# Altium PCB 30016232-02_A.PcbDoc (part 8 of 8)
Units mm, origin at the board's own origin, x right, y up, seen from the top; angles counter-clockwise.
Board outline 210 x 130 mm, 8 copper layers (1-TOP, 2-GND, 3-INTOP, 4-PWR, 5-PWR, 6-INBOT, 7-GND, 8-BOTTOM), stack 1.646 mm thick; 754 components, 649 nets, 2976 pads, 2161 vias.
Unrouted connection lines stored in the file: 22.
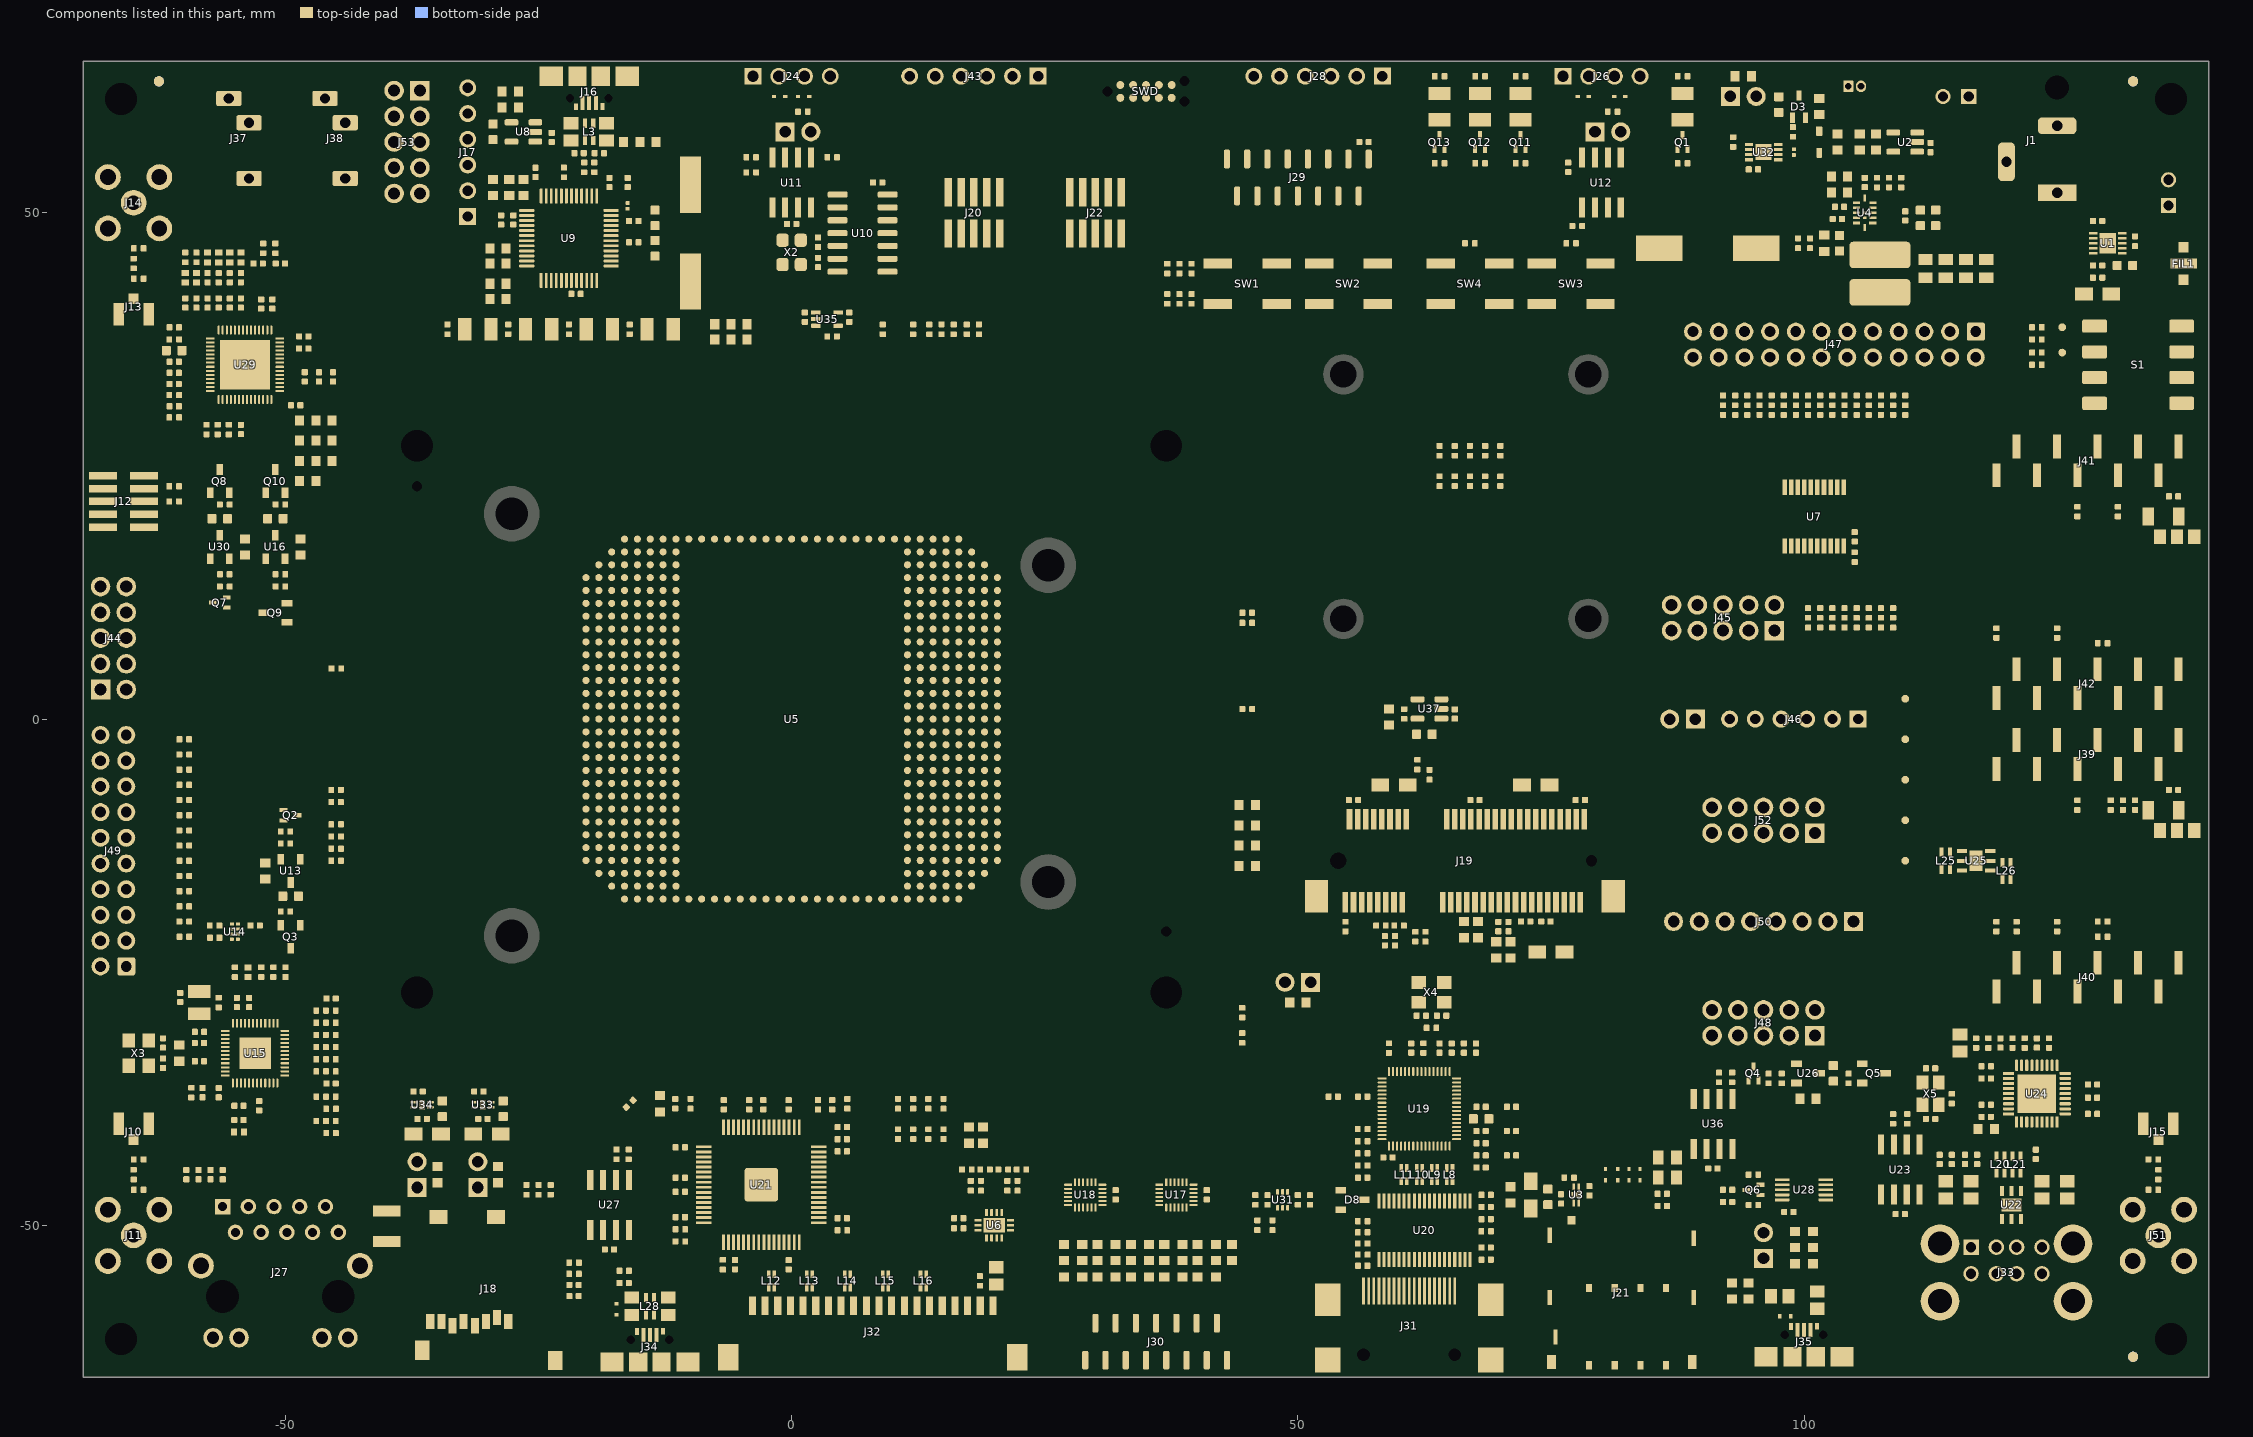
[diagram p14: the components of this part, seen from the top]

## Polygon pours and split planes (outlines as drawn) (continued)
NetJ6_2 on 1-TOP "NetJ6_2" (solid, remove dead copper, pour order 30): 45,-11.7 45.2,-11.5 49,-11.5 49.8,-12.3 49.8,-29.1 49.5,-29.4 46.4,-29.4 45,-28
GND on 1-TOP "GND" (solid, remove dead copper, pour order 28): 108.8,49.3 108.8,47.6 109,47.4 110.3,47.4 110.8,46.9 110.8,44.8 111,44.6 119,44.6 119.2,44.8 119.2,47.3 117,49.5 109,49.5
VIN_PROT on 1-TOP "VIN_PROT" (solid, remove dead copper, pour order 26): 107.1,49.9 110.283,49.9 110.783,49.4 113.7,49.4 114.1,49.8 114.1,52 113.9,52.2 110.2,52.2 110,52 109.2,52
3V3_CODEC on 1-TOP "3V3_USB" (solid, remove dead copper, pour order 20): -54.3,21.5 -53,20.2 -53,17.2 -53.2,17 -57,17 -57.2,17.2 -57.2,19.8 -55.5,21.5
1V8_SOM_EXT on 1-TOP "3V3_SOM_EXT" (solid, remove dead copper, pour order 18): -48.8,12.3 -47.5,13.6 -47.5,16.6 -47.7,16.8 -50.4,16.8 -50.6,16.6 -50.6,12.5 -50.4,12.3
1V8_CODEC on 1-TOP "3V3_USB" (solid, remove dead copper, pour order 16): -48.8,21.5 -47.5,20.2 -47.5,17.2 -47.7,17 -51.5,17 -51.7,17.2 -51.7,19.8 -50,21.5
3V3_ETH on 1-TOP "3V3_USB" (solid, remove dead copper, pour order 12): -52,-19.2 -53,-18.2 -53,-15.2 -52.8,-15 -49,-15 -48.8,-15.2 -48.8,-17.5 -50.5,-19.2
3V3_USB on 1-TOP "3V3_USB" (solid, remove dead copper, pour order 10): 104.7,-37.5 103.7,-38.5 100.7,-38.5 100.5,-38.3 100.5,-34.5 100.7,-34.3 103,-34.3 104.7,-36
VIN on 1-TOP "VIN" (solid, remove dead copper, pour order 6): 131.6,42.9 134,40.5 138.5,40.5 139,41 139,43.5 138.6,43.9 135.8,43.9 135.5,44.2 135.5,45.5 133.7,47.3 131,47.3 131,45.6 131.2,45.4 131.4,45.4 131.6,45.2
CT on 1-TOP "AGND" (solid, remove dead copper, pour order 2): -60.5,-45.2 -60.3,-45 -55.7,-45 -55.5,-45.2 -55.5,-48 -56.9,-48 -56.9,-47.2 -57.6,-46.5 -60,-46.5 -60.5,-46
GND on 3-INTOP "GND_PLANE" (solid, remove dead copper, pour order 60): -70,-65 140,-65 140,65 -70,65
5V_OUT_HDMI on 3-INTOP "5V_OUT_HDMI" (solid, remove dead copper, pour order 46): 54.5,-54.5 55.5,-55.5 67.5,-55.5 68.5,-54.5 68.5,-51 67.5,-50 55.5,-50 54.5,-51
GND on 8-BOTTOM "GND_PLANE" (solid, remove dead copper, pour order 64): -70,-65 140,-65 140,65 -70,65
3V3_RF on 8-BOTTOM "3V3_RF" (solid, remove dead copper, pour order 48): -18.872,2.337 -14.173,2.337 -13.767,2.743 -13.767,7.267 -14.3,7.8 -45.7,7.8 -47,6.5 -32,6.5 -29.107,3.607 -19.482,3.607 -19.253,3.378 -19.253,2.718
GND on 8-BOTTOM "GND" (solid, remove dead copper, pour order 50): 122,57 122.5,56.5 127.5,56.5 128,57 128,60 127.5,60.5 122.5,60.5 122,60
NetR34_2 on 8-BOTTOM "NetR34_2" (solid, remove dead copper, pour order 56): 23.443,-11.557 14.351,-11.557 13.97,-11.176 13.97,-9.144 14.351,-8.763 22.763,-8.763 24.5,-10.5
NetR33_2 on 8-BOTTOM "NetR33_2" (solid, remove dead copper, pour order 54): 23.241,-7.747 15.621,-7.747 15.24,-7.366 15.24,-5.334 15.621,-4.953 21.844,-4.953 23.241,-6.35
GND on 6-INBOT "GND_PLANE" (solid, remove dead copper, pour order 58): -70,-65 140,-65 140,65 -70,65
GND on 2-GND (split plane): 139.598,-64.598 -69.598,-64.598 -69.598,64.598 139.598,64.598
3V3 on 4-PWR (split plane): 48.893,21.893 48.924,21.869 48.961,21.854 49,21.849 75.1,21.849 75.139,21.854 75.176,21.869 75.207,21.893 85.163,31.849 104.849,31.849 104.849,19 104.854,18.961 104.869,18.924 104.893,18.893 108.349,15.437 108.349,8.563 104.937,5.151 59,5.151 58.961,5.146 58.924,5.131 58.893,5.107 44.937,-8.849 37,-8.849 36.961,-8.854 36.924,-8.869 36.893,-8.893 6.5,-39.286 5.107,-37.893 5.076,-37.869 5.061,-37.863 5.039,-37.854 5,-37.849 -18,-37.849 -18.039,-37.854 -18.065,-37.865 -18.076,-37.869 -18.107,-37.893 -22.063,-41.849 -35.937,-41.849 -37.849,-39.937 -37.849,-23 -37.854,-22.961 -37.863,-22.939 -37.869,-22.924 -37.893,-22.893 -47.849,-12.937 -47.849,5.437 -28.437,24.849 -10.5,24.849 -10.461,24.854 -10.439,24.863 -10.424,24.869 -10.393,24.893 5.063,40.349 30.437,40.349
3V3_SOM_EXT on 4-PWR (split plane): 111.849,56 111.854,55.961 111.863,55.939 111.869,55.924 111.893,55.893 112.893,54.893 112.924,54.869 112.961,54.854 113,54.849 129.937,54.849 134.849,49.937 134.849,-44.937 127.937,-51.849 95,-51.849 94.961,-51.854 94.924,-51.869 94.893,-51.893 93.893,-52.893 93.869,-52.924 93.854,-52.961 93.849,-53 93.849,-64.598 -69.598,-64.598 -69.598,64.598 111.849,64.598
3V3_ETH on 4-PWR (split plane): -50.651,-16.563 -50.651,-38.437 -54.063,-41.849 -55.937,-41.849 -60.849,-36.937 -60.849,-24.063 -52.937,-16.151 -51.063,-16.151
3V3_CODEC on 4-PWR (split plane): -45.151,37.937 -45.151,20.563 -47.563,18.151 -60.437,18.151 -60.849,18.563 -60.849,34.437 -56.437,38.849 -46.063,38.849
3V3_BOARD on 4-PWR (split plane): 118.349,42.937 118.349,39.863 115.393,36.907 115.369,36.876 115.354,36.839 115.349,36.8 115.349,35 115.354,34.961 115.369,34.924 115.393,34.893 127.849,22.437 127.849,-16.437 125.437,-18.849 116.063,-18.849 104.107,-6.893 104.076,-6.869 104.061,-6.863 104.039,-6.854 104,-6.849 98,-6.849 97.961,-6.854 97.924,-6.869 97.893,-6.893 97.163,-7.623 97.139,-7.654 97.124,-7.691 97.119,-7.73 97.119,-15.667 89.937,-22.849 81,-22.849 80.961,-22.854 80.924,-22.869 80.893,-22.893 74.937,-28.849 24.5,-28.849 24.461,-28.854 24.439,-28.863 24.424,-28.869 24.393,-28.893 18.893,-34.393 18.869,-34.424 18.854,-34.461 18.849,-34.5 18.849,-49.937 17.937,-50.849 17.063,-50.849 16.151,-49.937 16.151,-47.3 16.146,-47.261 16.131,-47.224 16.107,-47.193 11.557,-42.643 11.526,-42.619 11.511,-42.613 11.489,-42.604 11.45,-42.599 9.813,-42.599 6.714,-39.5 37.063,-9.151 45,-9.151 45.039,-9.146 45.076,-9.131 45.107,-9.107 59.063,4.849 105,4.849 105.039,4.854 105.076,4.869 105.107,4.893 108.607,8.393 108.631,8.424 108.646,8.461 108.651,8.5 108.651,15.5 108.646,15.539 108.631,15.576 108.607,15.607 105.151,19.063 105.151,41.937 106.563,43.349 117.937,43.349
VIN on 4-PWR (split plane): 139.598,-64.598 94.151,-64.598 94.151,-53.063 95.063,-52.151 128,-52.151 128.039,-52.146 128.061,-52.137 128.076,-52.131 128.107,-52.107 135.107,-45.107 135.131,-45.076 135.146,-45.039 135.151,-45 135.151,50 135.146,50.039 135.137,50.061 135.131,50.076 135.107,50.107 130.107,55.107 130.076,55.131 130.039,55.146 130,55.151 113.063,55.151 112.151,56.063 112.151,64.598 139.598,64.598
3V3_DBG on 4-PWR (split plane): -14.151,44.937 -14.151,40.063 -15.063,39.151 -33.937,39.151 -34.849,40.063 -34.849,47.937 -29.437,53.349 -22.563,53.349
NetC132_2 on 4-PWR (split plane): 127.849,-36.563 127.849,-39.006 124.506,-42.349 114.151,-42.349 114.151,-34.063 115.063,-33.151 116.937,-33.151 118.393,-34.607 118.424,-34.631 118.435,-34.635 118.461,-34.646 118.5,-34.651 120.8,-34.651 120.839,-34.646 120.861,-34.637 120.876,-34.631 120.907,-34.607 123.4,-32.114
3V3_USB on 4-PWR (split plane): 123.186,-31.9 120.737,-34.349 118.563,-34.349 117.107,-32.893 117.076,-32.869 117.039,-32.854 117,-32.849 115,-32.849 114.961,-32.854 114.924,-32.869 114.893,-32.893 113.893,-33.893 113.869,-33.924 113.863,-33.939 113.854,-33.961 113.849,-34 113.849,-42.349 105.563,-42.349 101.651,-38.437 101.651,-36.563 108.563,-29.651 120.937,-29.651
VDDH1 on 5-PWR (split plane): -55.107,-38.107 -55.076,-38.131 -55.065,-38.135 -55.039,-38.146 -55,-38.151 -52,-38.151 -51.961,-38.146 -51.924,-38.131 -51.893,-38.107 -50.437,-36.651 -43.151,-36.651 -43.151,-43.349 -54.437,-43.349 -60.849,-36.937 -60.849,-35.151 -58.063,-35.151
5V on 5-PWR (split plane): 4.849,52.063 -2.063,45.151 -13.937,45.151 -22.393,53.607 -22.424,53.631 -22.461,53.646 -22.5,53.651 -29.5,53.651 -29.539,53.646 -29.576,53.631 -29.607,53.607 -35.107,48.107 -35.131,48.076 -35.137,48.061 -35.146,48.039 -35.151,48 -35.151,39.151 -56.5,39.151 -56.539,39.146 -56.576,39.131 -56.607,39.107 -61.107,34.607 -61.131,34.576 -61.146,34.539 -61.151,34.5 -61.151,-37 -61.146,-37.039 -61.131,-37.076 -61.107,-37.107 -54.607,-43.607 -54.576,-43.631 -54.539,-43.646 -54.5,-43.651 -43.063,-43.651 -36.607,-50.107 -36.576,-50.131 -36.561,-50.137 -36.539,-50.146 -36.5,-50.151 -14.563,-50.151 -10.607,-54.107 -10.576,-54.131 -10.539,-54.146 -10.5,-54.151 18,-54.151 18.039,-54.146 18.061,-54.137 18.076,-54.131 18.107,-54.107 19.563,-52.651 20.937,-52.651 22.393,-54.107 22.424,-54.131 22.461,-54.146 22.5,-54.151 67.5,-54.151 67.539,-54.146 67.576,-54.131 67.607,-54.107 69.607,-52.107 69.631,-52.076 69.646,-52.039 69.651,-52 69.651,-50.9 69.646,-50.861 69.631,-50.824 69.607,-50.793 67.151,-48.337 67.151,-46.863 71.107,-42.907 71.131,-42.876 71.146,-42.839 71.151,-42.8 71.151,-30.151 78.937,-30.151 79.849,-31.063 79.849,-32.437 74.893,-37.393 74.869,-37.424 74.854,-37.461 74.849,-37.5 74.849,-50.937 68.937,-56.849 -12.437,-56.849 -16.893,-52.393 -16.924,-52.369 -16.939,-52.363 -16.961,-52.354 -17,-52.349 -18,-52.349 -18.039,-52.354 -18.065,-52.365 -18.076,-52.369 -18.107,-52.393 -19.107,-53.393 -19.131,-53.424 -19.146,-53.461 -19.151,-53.5 -19.151,-64.598 -69.598,-64.598 -69.598,64.598 4.849,64.598
1V8_SOM_EXT on 5-PWR (split plane): 22.849,49.5 22.854,49.461 22.863,49.439 22.869,49.424 22.893,49.393 30.349,41.937 30.349,40.651 5,40.651 4.961,40.646 4.924,40.631 4.893,40.607 -10.563,25.151 -28.5,25.151 -28.539,25.146 -28.565,25.135 -28.576,25.131 -28.607,25.107 -48.107,5.607 -48.131,5.576 -48.137,5.561 -48.146,5.539 -48.151,5.5 -48.151,-13 -48.146,-13.039 -48.137,-13.061 -48.131,-13.076 -48.107,-13.107 -38.151,-23.063 -38.151,-40 -38.146,-40.039 -38.137,-40.061 -38.131,-40.076 -38.107,-40.107 -36.107,-42.107 -36.076,-42.131 -36.039,-42.146 -36,-42.151 -22,-42.151 -21.961,-42.146 -21.939,-42.137 -21.924,-42.131 -21.893,-42.107 -17.937,-38.151 4.937,-38.151 5.893,-39.107 5.924,-39.131 5.961,-39.146 6,-39.151 7,-39.151 7.039,-39.146 7.061,-39.137 7.076,-39.131 7.107,-39.107 9.063,-37.151 43,-37.151 43.039,-37.146 43.061,-37.137 43.076,-37.131 43.107,-37.107 50.063,-30.151 70.849,-30.151 70.849,-42.737 66.893,-46.693 66.869,-46.724 66.863,-46.739 66.854,-46.761 66.849,-46.8 66.849,-48.4 66.854,-48.439 66.863,-48.461 66.869,-48.476 66.893,-48.507 69.349,-50.963 69.349,-51.937 67.437,-53.849 22.563,-53.849 21.107,-52.393 21.076,-52.369 21.061,-52.363 21.039,-52.354 21,-52.349 19.5,-52.349 19.461,-52.354 19.424,-52.369 19.393,-52.393 17.937,-53.849 -10.437,-53.849 -14.393,-49.893 -14.424,-49.869 -14.439,-49.863 -14.461,-49.854 -14.5,-49.849 -36.437,-49.849 -42.849,-43.437 -42.849,-28 -42.854,-27.961 -42.865,-27.935 -42.869,-27.924 -42.893,-27.893 -43.893,-26.893 -43.924,-26.869 -43.961,-26.854 -44,-26.849 -50.349,-26.849 -50.349,-23.5 -50.354,-23.461 -50.369,-23.424 -50.393,-23.393 -50.893,-22.893 -50.924,-22.869 -50.939,-22.863 -50.961,-22.854 -51,-22.849 -60.849,-22.849 -60.849,17.849 -47.5,17.849 -47.461,17.854 -47.439,17.863 -47.424,17.869 -47.393,17.893 -44.893,20.393 -44.869,20.424 -44.854,20.461 -44.849,20.5 -44.849,38.849 -15,38.849 -14.961,38.854 -14.924,38.869 -14.893,38.893 -13.893,39.893 -13.869,39.924 -13.854,39.961 -13.849,40 -13.849,44.849 -2,44.849 -1.961,44.854 -1.939,44.863 -1.924,44.869 -1.893,44.893 5.107,51.893 5.131,51.924 5.137,51.939 5.146,51.961 5.151,52 5.151,64.598 22.849,64.598
NetC75_2 on 5-PWR (split plane): -50.651,-36.437 -52.063,-37.849 -54.937,-37.849 -57.893,-34.893 -57.924,-34.869 -57.939,-34.863 -57.961,-34.854 -58,-34.849 -60.849,-34.849 -60.849,-30.051 -54.9,-30.051 -54.861,-30.046 -54.824,-30.031 -54.793,-30.007 -54.093,-29.307 -54.069,-29.276 -54.054,-29.239 -54.049,-29.2 -54.049,-25.763 -53.437,-25.151 -50.651,-25.151
DVDDL1 on 5-PWR (split plane): -50.651,-23.563 -50.651,-24.849 -53.5,-24.849 -53.539,-24.854 -53.576,-24.869 -53.607,-24.893 -54.307,-25.593 -54.331,-25.624 -54.346,-25.661 -54.351,-25.7 -54.351,-29.137 -54.963,-29.749 -60.849,-29.749 -60.849,-23.151 -51.063,-23.151
1V8_CODEC on 5-PWR (split plane): -45.151,20.563 -47.563,18.151 -60.849,18.151 -60.849,34.437 -56.437,38.849 -45.151,38.849
VDDIO1 on 5-PWR (split plane): -43.151,-28.063 -43.151,-36.349 -50.349,-36.349 -50.349,-27.151 -44.063,-27.151
1V8 on 5-PWR (split plane): 45.349,25.437 45.349,10.5 45.354,10.461 45.363,10.439 45.369,10.424 45.393,10.393 68.893,-13.107 68.924,-13.131 68.961,-13.146 69,-13.151 102,-13.151 102.039,-13.146 102.061,-13.137 102.076,-13.131 102.107,-13.107 105.107,-10.107 105.131,-10.076 105.146,-10.039 105.151,-10 105.151,39.349 121.937,39.349 122.849,38.437 122.849,-2.437 105.437,-19.849 54,-19.849 53.961,-19.854 53.924,-19.869 53.893,-19.893 49.893,-23.893 49.869,-23.924 49.854,-23.961 49.849,-24 49.849,-29.937 42.937,-36.849 9,-36.849 8.961,-36.854 8.924,-36.869 8.893,-36.893 6.937,-38.849 6.063,-38.849 5.107,-37.893 5.076,-37.869 5.061,-37.863 5.039,-37.854 5,-37.849 -18,-37.849 -18.039,-37.854 -18.065,-37.865 -18.076,-37.869 -18.107,-37.893 -22.063,-41.849 -35.937,-41.849 -37.849,-39.937 -37.849,-23 -37.854,-22.961 -37.869,-22.924 -37.893,-22.893 -47.849,-12.937 -47.849,5.437 -28.437,24.849 -10.5,24.849 -10.461,24.854 -10.439,24.863 -10.424,24.869 -10.393,24.893 5.063,40.349 30.437,40.349
VIN_PROT on 5-PWR (split plane): 139.598,-64.598 -18.849,-64.598 -18.849,-53.563 -17.937,-52.651 -17.063,-52.651 -12.607,-57.107 -12.576,-57.131 -12.539,-57.146 -12.5,-57.151 69,-57.151 69.039,-57.146 69.061,-57.137 69.076,-57.131 69.107,-57.107 75.107,-51.107 75.131,-51.076 75.146,-51.039 75.151,-51 75.151,-37.563 80.107,-32.607 80.131,-32.576 80.146,-32.539 80.151,-32.5 80.151,-31 80.146,-30.961 80.131,-30.924 80.107,-30.893 79.107,-29.893 79.076,-29.869 79.061,-29.863 79.039,-29.854 79,-29.849 50.151,-29.849 50.151,-24.063 54.063,-20.151 105.5,-20.151 105.539,-20.146 105.561,-20.137 105.576,-20.131 105.607,-20.107 123.107,-2.607 123.131,-2.576 123.146,-2.539 123.151,-2.5 123.151,38.5 123.146,38.539 123.137,38.561 123.131,38.576 123.107,38.607 122.107,39.607 122.076,39.631 122.039,39.646 122,39.651 105.151,39.651 105.151,64.598 139.598,64.598
VSYS on 5-PWR (split plane): 44.849,-10.063 44.849,-13.184 17.931,-13.184 17.931,-9.588 18.478,-9.041 43.827,-9.041
1V8_SOM_EXT on 5-PWR (split plane): -14.151,44.937 -14.151,40.063 -15.063,39.151 -34.849,39.151 -34.849,47.937 -29.437,53.349 -22.563,53.349
VSYS2 on 5-PWR (split plane): 44.849,-16.937 40.937,-20.849 19.158,-20.849 15.391,-17.082 15.391,-16.8 15.391,-14.668 16.573,-13.486 44.849,-13.486
VCC_MCA on 5-PWR (split plane): 104.849,-9.937 101.937,-12.849 69.063,-12.849 45.651,10.563 45.651,25.5 45.646,25.539 45.635,25.565 45.631,25.576 45.607,25.607 30.651,40.563 30.651,42 30.646,42.039 30.631,42.076 30.607,42.107 23.151,49.563 23.151,64.598 104.849,64.598
GND on 7-GND (split plane): 139.598,-64.598 -69.598,-64.598 -69.598,64.598 139.598,64.598

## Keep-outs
Keep-Out Layer:
  the board outline again, w0.15

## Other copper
1-TOP:
  pour cut-out: -57.5,-47 -60.5,-50 -60.5,-65 -41,-65 -41,-52.5 -45.5,-52.5 -45.5,-47
  pour cut-out: -20.5,-61 -20.5,-65 -7.5,-65 -7.5,-61
  pour cut-out: 110,-51 110,-65 130,-65 130,-51 127.5,-48.5 112.5,-48.5
  pour cut-out: 50.5,-54.5 50.5,-65 71.5,-65 71.5,-54.5
  region net 1V8: -37.6,-37.8 -37.6,-34 -37.4,-33.8 -35.4,-33.8 -35.2,-34 -35.2,-36 -35.4,-36.2 -36.9,-36.2 -37.1,-36.4 -37.1,-37.8
  region net NetC191_1: -35.4,-38.4 -35.4,-38.8 -35.9,-38.8 -35.9,-38.4
  region net 3V3: -31.6,-37.8 -31.6,-34 -31.4,-33.8 -29.4,-33.8 -29.2,-34 -29.2,-36 -29.4,-36.2 -30.9,-36.2 -31.1,-36.4 -31.1,-37.8
  region net NetC187_1: -29.4,-38.4 -29.4,-38.8 -29.9,-38.8 -29.9,-38.4
  region net 3V3_BOARD: 110.9,43.2 110.9,41.1 109.1,41.1 109.1,43.2
  region net VIN_PROT: 128.8,45.9 128.8,45.6 128.2,45.6 128.2,45.9
  region net VIN: 131.2,45.9 131.2,45.6 131.8,45.6 131.8,45.9
  pour cut-out: -58,39 -50,39 -50,31 -58,31
  pour cut-out: -26,51.5 -18,51.5 -18,43.5 -26,43.5
  pour cut-out: 58.5,-35 58.5,-42 65.5,-42 65.5,-35
  pour cut-out: -8,-41 -8,-51 2,-51 2,-41
  pour cut-out: -56,-36 -50,-36 -50,-30 -56,-30
  pour cut-out: -22,-14 -17,-19 17,-19 21,-15 21,15 17,19 -17,19 -22,14
  region net VIN_PROT: 126.5,40.5 126.5,47 124.5,47 119.3,52.2 113.8,52.2 113.8,49.8 117.2,49.8
  region net NetL1_1: 108.6,49.4 108.6,45.85 107.4,45.85 107.4,49.2 107.2,49.4 106,49.4 106,49.6 107.2,49.6 107.3,49.7 108.3,49.7
  region net VIN_PROT: 108,49.9 108,50.4 107.6,50.4 107.3,50.1 106,50.1 106,49.9
  region net CT: -56.9,-47 -56.9,-48 -55.5,-48 -55.5,-47
  text "30016232-02_TOP" at 7.5,56 h1.2
8-BOTTOM:
  text "30016232-02_BOT" at 25,56 h1.2
4-PWR (plane layer: these items are gaps in the copper):
  lines w0.3: 94,-65 94,-53 95,-52 128,-52 135,-45 135,50 130,55 113,55 112,56 112,65 ; 105,32 85.1,32 75.1,22 49,22 30.5,40.5 5,40.5 -10.5,25 -28.5,25 -48,5.5 -48,-13 -38,-23 -38,-40 -36,-42 -22,-42 -18,-38 5,-38 6.5,-39.5 ; 114,-42.5 114,-34 115,-33 117,-33 118.5,-34.5 120.8,-34.5 123.4,-31.9 ; 6.5,-39.5 9.75,-42.75 11.45,-42.75 16,-47.3 16,-50 17,-51 18,-51 19,-50 19,-34.5 24.5,-29 75,-29 81,-23 90,-23 97.27,-15.73 97.27,-7.73 98,-7 104,-7 116,-19 125.5,-19 128,-16.5 128,22.5 115.5,35 115.5,36.8 118.5,39.8 118.5,43 118,43.5 106.5,43.5 105,42 105,19 108.5,15.5 108.5,8.5 105,5 59,5 45,-9 37,-9 6.5,-39.5 ; 123.4,-31.9 121,-29.5 108.5,-29.5 101.5,-36.5 101.5,-38.5 105.5,-42.5 124.568,-42.5 128,-39.068 128,-36.5 123.4,-31.9 ; -61,-37 -61,-24 -53,-16 -51,-16 -50.5,-16.5 -50.5,-38.5 -54,-42 -56,-42 -61,-37 ; -61,18.5 -60.5,18 -47.5,18 -45,20.5 -45,38 -46,39 -56.5,39 -61,34.5 -61,18.5 ; -35,40 -34,39 -15,39 -14,40 -14,45 -22.5,53.5 -29.5,53.5 -35,48 -35,40
5-PWR (plane layer: these items are gaps in the copper):
  lines w0.3: -61,-29.9 -54.9,-29.9 -54.2,-29.2 -54.2,-25.7 -53.5,-25 -50.5,-25 ; -61,18 -47.5,18 -45,20.5 -45,39 ; -50.5,-27 -44,-27 -43,-28 -43,-43.5 ; -43,-36.5 -50.5,-36.5 ; -19,-65 -19,-53.5 -18,-52.5 -17,-52.5 -12.5,-57 69,-57 75,-51 75,-37.5 80,-32.5 80,-31 79,-30 71,-30 ; 5,65 5,52 -2,45 -14,45 ; 17.78,-13.335 17.78,-9.525 18.415,-8.89 43.89,-8.89 45,-10 45,-17 41,-21 19.095,-21 15.24,-17.145 15.24,-16.8 15.24,-14.605 16.51,-13.335 45,-13.335 ; 23,65 23,49.5 30.5,42 30.5,40.5 ; 105,39.5 122,39.5 123,38.5 123,-2.5 105.5,-20 54,-20 50,-24 50,-30 ; 105,65 105,-10 102,-13 69,-13 45.5,10.5 45.5,25.5 30.5,40.5 ; -61,-37 -54.5,-43.5 -43,-43.5 ; -61,-37 -61,-35 ; -61,-37 -61,34.5 -56.5,39 -45,39 ; -61,-35 -58,-35 -55,-38 -52,-38 -50.5,-36.5 ; -61,-35 -61,-23 -51,-23 -50.5,-23.5 -50.5,-36.5 ; -45,39 -35,39 ; -43,-43.5 -36.5,-50 -14.5,-50 -10.5,-54 18,-54 19.5,-52.5 21,-52.5 22.5,-54 67.5,-54 69.5,-52 69.5,-50.9 67,-48.4 67,-46.8 71,-42.8 71,-30 ; -35,39 -35,48 -29.5,53.5 -22.5,53.5 -14,45 ; -35,39 -15,39 -14,40 -14,45 ; 30.5,40.5 5,40.5 -10.5,25 -28.5,25 -48,5.5 -48,-13 -38,-23 -38,-40 -36,-42 -22,-42 -18,-38 5,-38 6,-39 7,-39 9,-37 43,-37 50,-30 ; 50,-30 71,-30

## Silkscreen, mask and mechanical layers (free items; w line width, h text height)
Top Overlay:
  drawing of 34 lines, arcs and shapes, not listed
  text "CONSOLE" at -16,60.5 h1
  text "CAN" at -5.5,60.5 h1
  text "COIN-CELL" at 102.5,60 h1
  text "RS485" at 74.9,59.8 h1
  text "LED3" at 62.6,58.7 h1 r90
  text "LED2" at 66.6,58.7 h1 r90
  text "LED1" at 70.6,58.7 h1 r90
  text "MIPI Camera" at 49,49 h1
  text "POWER" at 42.5,38.5 h1
  text "RESET" at 52.5,38.5 h1
  text "USER2" at 64.5,38.5 h1
  text "USER1" at 74.5,38.5 h1
  text "Table in" at 119.8,33.1 h1
  text "bottom side" at 117,31.6 h1
  text "I2C_3V3" at 63.8,27.7 h1
  text "XBEE USER" at 123.5,14 h1
  text "XBEE CELLULAR" at 122,-15 h1
  text "I2C_1V8" at 9.8,-36.8 h1
  text "LVDS Display" at 3.6,-53.1 h1
  text "MIPI Display" at 30.3,-57.9 h1
  text "RECOVERY" at 107,-63 h1 r90
Bottom Overlay:
  lines w0.255: -61.132,-5.095 -14,-5.095 ; -61.132,-2.548 -14,-2.548 ; -61.132,0 -14,0 ; -61.132,2.548 -14,2.548 ; -61.132,5.095 -14,5.095 ; -61.132,7.643 -14,7.643 ; -39.477,-7.643 -39.477,10.191 ; -33.107,-7.643 -33.107,10.191 ; -26.738,-7.643 -26.738,10.191 ; -20.369,-7.643 -20.369,10.191 ; -61.132,-7.643 -14,-7.643 -14,10.191 -61.132,10.191 -61.132,-7.643
  lines w0.521: -20.25,42.606 -14.092,42.606 ; -20.25,44.659 -14.092,44.659 ; -20.25,46.712 -14.092,46.712 ; -20.25,48.764 -14.092,48.764 ; -17.171,40.554 -17.171,50.817 ; 12.591,42.606 18.748,42.606 ; 12.591,44.659 18.748,44.659 ; 12.591,46.712 18.748,46.712 ; 12.591,48.764 18.748,48.764 ; 15.67,40.554 15.67,50.817 ; 45.431,42.606 51.589,42.606 ; 45.431,44.659 51.589,44.659 ; 45.431,46.712 51.589,46.712 ; 45.431,48.764 51.589,48.764 ; 48.51,40.554 48.51,50.817 ; 78.272,42.606 84.43,42.606 ; 78.272,44.659 84.43,44.659 ; 78.272,46.712 84.43,46.712 ; 78.272,48.764 84.43,48.764 ; 81.351,40.554 81.351,50.817 ; 111.113,42.606 117.27,42.606 ; 111.113,44.659 117.27,44.659 ; 111.113,46.712 117.27,46.712 ; 111.113,48.764 117.27,48.764 ; 114.191,40.554 114.191,50.817 ; -20.25,40.554 -20.25,50.817 -14.092,50.817 -14.092,40.554 -20.25,40.554 ; 12.591,40.554 18.748,40.554 18.748,50.817 12.591,50.817 12.591,40.554 ; 45.431,40.554 51.589,40.554 51.589,50.817 45.431,50.817 45.431,40.554 ; 78.272,40.554 84.43,40.554 84.43,50.817 78.272,50.817 78.272,40.554 ; 111.113,40.554 117.27,40.554 117.27,50.817 111.113,50.817 111.113,40.554
  lines w0.572: 33.821,-13.573 40.579,-13.573 ; 33.821,-11.321 40.579,-11.321 ; 33.821,-9.068 40.579,-9.068 ; 33.821,-6.816 40.579,-6.816 ; 33.821,-4.563 40.579,-4.563 ; 33.821,-2.31 40.579,-2.31 ; 33.821,-0.058 40.579,-0.058 ; 33.821,2.195 40.579,2.195 ; 33.821,4.447 40.579,4.447 ; 37.2,-15.826 37.2,6.7 ; 67.61,-18.079 74.368,-18.079 ; 67.61,-15.826 74.368,-15.826 ; 67.61,-13.573 74.368,-13.573 ; 67.61,-11.321 74.368,-11.321 ; 67.61,-9.068 74.368,-9.068 ; 67.61,-6.816 74.368,-6.816 ; 67.61,-4.563 74.368,-4.563 ; 67.61,-2.31 74.368,-2.31 ; 67.61,-0.058 74.368,-0.058 ; 67.61,2.195 74.368,2.195 ; 67.61,4.447 74.368,4.447 ; 70.989,-20.331 70.989,6.7 ; 33.821,-15.826 40.579,-15.826 40.579,6.7 33.821,6.7 33.821,-15.826 ; 67.61,-20.331 67.61,6.7 74.368,6.7 74.368,-20.331 67.61,-20.331
  lines w0.575: 8.48,-50.082 11.309,-50.082 ; 8.48,-47.819 11.309,-47.819 ; 8.48,-45.556 11.309,-45.556 ; 8.48,-43.293 11.309,-43.293 ; 8.48,-41.03 11.309,-41.03 ; 8.48,-38.767 11.309,-38.767 ; 8.48,-36.504 11.309,-36.504 ; 26.584,-45.556 29.413,-45.556 ; 26.584,-43.293 29.413,-43.293 ; 26.584,-41.03 29.413,-41.03 ; 26.584,-38.767 29.413,-38.767 ; 26.584,-36.504 29.413,-36.504 ; 44.689,-45.556 47.517,-45.556 ; 44.689,-43.293 47.517,-43.293 ; 44.689,-41.03 47.517,-41.03 ; 44.689,-38.767 47.517,-38.767 ; 44.689,-36.504 47.517,-36.504 ; 62.793,-45.556 65.621,-45.556 ; 62.793,-43.293 65.621,-43.293 ; 62.793,-41.03 65.621,-41.03 ; 62.793,-38.767 65.621,-38.767 ; 62.793,-36.504 65.621,-36.504 ; 8.48,-52.346 8.48,-34.241 11.309,-34.241 11.309,-52.346 8.48,-52.346 ; 26.584,-47.819 26.584,-34.241 29.413,-34.241 29.413,-47.819 26.584,-47.819 ; 44.689,-47.819 44.689,-34.241 47.517,-34.241 47.517,-47.819 44.689,-47.819 ; 62.793,-47.819 65.621,-47.819 65.621,-34.241 62.793,-34.241 62.793,-47.819
  text "J53" at -14.092,51.843 h2.05
  text "J52" at 18.748,51.843 h2.05
  text "J48" at 51.589,51.843 h2.05
  text "J45" at 84.43,51.843 h2.05
  text "J44" at 117.27,51.843 h2.05
  text "GND" at 11.4,49.3 h0.82
  text "LINE1_IN_R" at -21.789,49.277 h0.82
  text "1" at -18.197,49.277 h0.82
  text "2" at -15.118,49.277 h0.82
  text "LINE1_IN_L" at -5.369,49.277 h0.82
  text "1" at 14.643,49.277 h0.82
  text "2" at 17.722,49.277 h0.82
  text "EXP_I2C_SCL" at 43.892,49.277 h0.82
  text "1" at 47.484,49.277 h0.82
  text "2" at 50.563,49.277 h0.82
  text "I2C2_SCL_3V3" at 62.365,49.277 h0.82
  text "UART3_TX" at 76.733,49.277 h0.82
  text "1" at 80.324,49.277 h0.82
  text "2" at 83.403,49.277 h0.82
  text "XBEE1_UART_TX" at 95.719,49.277 h0.82
  text "BT_WAKEUP_HOST" at 109.573,49.277 h0.82
  text "1" at 113.165,49.277 h0.82
  text "2" at 116.244,49.277 h0.82
  text "VCC_MCA" at 25.1,49.2 h0.82
  text "BT_GPIO_2" at 125.6,49.2 h0.82
  text "LINE2_IN_R" at -21.789,47.225 h0.82
  text "3" at -18.197,47.225 h0.82
  text "4" at -15.118,47.225 h0.82
  text "LINE2_IN_L" at -5.369,47.225 h0.82
  text "3" at 14.643,47.225 h0.82
  text "4" at 17.722,47.225 h0.82
  text "EXP_I2C_SDA" at 43.892,47.225 h0.82
  text "3" at 47.484,47.225 h0.82
  text "4" at 50.563,47.225 h0.82
  text "I2C2_SDA_3V3" at 62.365,47.225 h0.82
  text "UART3_RX" at 76.733,47.225 h0.82
  text "3" at 80.324,47.225 h0.82
  text "4" at 83.403,47.225 h0.82
  text "XBEE1_UART_RX" at 95.719,47.225 h0.82
  text "BT_WAKEUP_SLAVE" at 109.573,47.225 h0.82
  text "3" at 113.165,47.225 h0.82
  text "4" at 116.244,47.225 h0.82
  text "5V" at 11.4,47.2 h0.82
  text "3V3_SOM_EXT" at 28.4,47.2 h0.82
  text "BT_GPIO_3" at 125.6,47.2 h0.82
  text "3V3_RF" at 24.3,45.2 h0.82
  text "BT_GPIO_5" at 125.6,45.2 h0.82
  text "LINE_OUT_R" at -21.789,45.172 h0.82
  text "5" at -18.197,45.172 h0.82
  text "6" at -15.118,45.172 h0.82
  text "LINE_OUT_L" at -5.369,45.172 h0.82
  text "5" at 14.643,45.172 h0.82
  text "6" at 17.722,45.172 h0.82
  text "EXP_I2C_IRQ_N" at 43.892,45.172 h0.82
  text "5" at 47.484,45.172 h0.82
  text "6" at 50.563,45.172 h0.82
  text "I2C3_SCL_1V8" at 62.365,45.172 h0.82
  text "GND" at 76.733,45.172 h0.82
  text "5" at 80.324,45.172 h0.82
  text "6" at 83.403,45.172 h0.82
  text "VCC_MCA" at 91.1,45.172 h0.82
  text "PCM_CLK" at 109.573,45.172 h0.82
  text "5" at 113.165,45.172 h0.82
  text "6" at 116.244,45.172 h0.82
  text "3V3_BOARD" at 11.4,45.1 h0.82
  text "1V8_SOM_EXT" at 11.4,43.2 h0.82
  text "SPKL_P" at -21.789,43.12 h0.82
  text "7" at -18.197,43.12 h0.82
  text "8" at -15.118,43.12 h0.82
  text "SPKL_N" at -7.935,43.12 h0.82
  text "7" at 14.643,43.12 h0.82
  text "8" at 17.722,43.12 h0.82
  text "VDDA_1V8" at 25.8,43.1 h0.82
  text "EXP_I2C_GPIO" at 43.892,43.12 h0.82
  text "7" at 47.484,43.12 h0.82
  text "8" at 50.563,43.12 h0.82
  text "I2C3_SDA_1V8" at 62.365,43.12 h0.82
  text "UART3_RTS_B" at 76.733,43.12 h0.82
  text "7" at 80.324,43.12 h0.82
  text "8" at 83.403,43.12 h0.82
  text "XBEE1_UART_RTS" at 96.745,43.12 h0.82
  text "PCM_IN" at 109.573,43.12 h0.82
  text "7" at 113.165,43.12 h0.82
  text "8" at 116.244,43.12 h0.82
  text "JTAG_SEL" at 124.9,43.1 h0.82
  text "LDO4" at 11.4,41.1 h0.82
  text "LDO5" at 22.6,41.1 h0.82
  text "GND" at 120.8,41.1 h0.82
  text "SPKR_P" at -21.789,41.067 h0.82
  text "9" at -18.197,41.067 h0.82
  text "10" at -15.118,41.067 h0.82
  text "SPKR_N" at -7.935,41.067 h0.82
  text "9" at 14.643,41.067 h0.82
  text "10" at 17.722,41.067 h0.82
  text "GND" at 43.892,41.067 h0.82
  text "9" at 47.484,41.067 h0.82
  text "10" at 50.563,41.067 h0.82
  text "GND" at 55.181,41.067 h0.82
  text "UART3_CTS_B" at 76.733,41.067 h0.82
  text "9" at 80.324,41.067 h0.82
  text "10" at 83.403,41.067 h0.82
  text "XBEE1_UART_CTS" at 96.745,41.067 h0.82
  text "PCM_OUT" at 109.573,41.067 h0.82
  text "9" at 113.165,41.067 h0.82
  text "10" at 116.244,41.067 h0.82
  text "S1" at -35.655,11.464 h2.55
  text "Description" at -40.113,8.152 h2.55
  text "SW1.1" at -33.235,8.152 h2.55
  text "SW1.2" at -27.12,8.152 h2.55
  text "SW1.3" at -20.751,8.152 h2.55
  text "SW1.4" at -14.382,8.152 h2.55
  text "J49" at 40.579,7.826 h2.25
  text "J47" at 74.368,7.826 h2.25
  text "Bot from eMMC" at -40.113,5.732 h2.55
  text "Open" at -33.744,5.732 h2.55
  text "Open" at -27.375,5.732 h2.55
  text "Open" at -21.006,5.732 h2.55
  text "-" at -17.185,5.732 h2.55
  text "WLAN_SD1_D0" at 32.132,5.011 h0.9
  text "2" at 36.074,5.011 h0.9
  text "1" at 39.453,5.011 h0.9
  text "3V3_RF" at 46.774,5.011 h0.9
  text "3V3_SOM_EXT" at 65.921,5.011 h0.9
  text "2" at 69.863,5.011 h0.9
  text "1" at 73.242,5.011 h0.9
  text "GND" at 78.31,5.011 h0.9
  text "Boot from MicroSD" at -40.113,3.185 h2.55
  text "Open" at -33.744,3.185 h2.55
  text "Close" at -27.375,3.185 h2.55
  text "Close" at -21.006,3.185 h2.55
  text "-" at -17.185,3.185 h2.55
  text "WLAN_SD1_D1" at 32.132,2.758 h0.9
  text "4" at 36.074,2.758 h0.9
  text "3" at 39.453,2.758 h0.9
  text "BT_UART1_TX" at 51.279,2.758 h0.9
  text "SAI1_RXFS" at 65.921,2.758 h0.9
  text "4" at 69.863,2.758 h0.9
  text "3" at 73.242,2.758 h0.9
  text "SAI1_TXFS" at 83.378,2.758 h0.9
  text "Boot from Fuses" at -40.113,0.637 h2.55
  text "Close" at -33.744,0.637 h2.55
  text "Open" at -27.375,0.637 h2.55
  text "-" at -23.554,0.637 h2.55
  text "-" at -17.185,0.637 h2.55
  text "WLAN_SD1_D2" at 32.132,0.505 h0.9
  text "6" at 36.074,0.505 h0.9
  text "5" at 39.453,0.505 h0.9
  text "BT_UART1_RX" at 51.279,0.505 h0.9
  text "SAI1_RXC" at 65.921,0.505 h0.9
  text "6" at 69.863,0.505 h0.9
  text "5" at 73.242,0.505 h0.9
  text "SAI1_TXC" at 82.815,0.505 h0.9
  text "WLAN_SD1_D3" at 32.132,-1.747 h0.9
  text "8" at 36.074,-1.747 h0.9
  text "7" at 39.453,-1.747 h0.9
  text "BT_UART1_RTS#" at 52.968,-1.747 h0.9
  text "SAI1_RXD0" at 65.921,-1.747 h0.9
  text "8" at 69.863,-1.747 h0.9
  text "7" at 73.242,-1.747 h0.9
  text "SAI1_TXD0" at 83.378,-1.747 h0.9
  text "Serial downloader" at -40.113,-1.911 h2.55
  text "Close" at -33.744,-1.911 h2.55
  text "Close" at -27.375,-1.911 h2.55
  text "-" at -23.554,-1.911 h2.55
  text "-" at -17.185,-1.911 h2.55
  text "WLAN_SD1_D4" at 32.132,-4 h0.9
  text "10" at 36.074,-4 h0.9
  text "9" at 39.453,-4 h0.9
  text "BT_UART1_CTS#" at 52.968,-4 h0.9
  text "SAI1_RXD1" at 65.921,-4 h0.9
  text "10" at 69.863,-4 h0.9
  text "9" at 73.242,-4 h0.9
  text "SAI1_TXD1" at 83.378,-4 h0.9
  text "MIPI connected to HDMI" at -40.113,-4.458 h2.55
  text "-" at -36.292,-4.458 h2.55
  text "-" at -29.923,-4.458 h2.55
  text "-" at -23.554,-4.458 h2.55
  text "Open" at -14.637,-4.458 h2.55
  text "WLAN_SD1_D5" at 32.132,-6.252 h0.9
  text "12" at 36.074,-6.252 h0.9
  text "11" at 39.453,-6.252 h0.9
  text "GND" at 44.521,-6.252 h0.9
  text "SAI1_RXD2" at 65.921,-6.252 h0.9
  text "12" at 69.863,-6.252 h0.9
  text "11" at 73.242,-6.252 h0.9
  text "SAI1_TXD2" at 83.378,-6.252 h0.9
  text "MIPI connected to LVDS" at -40.113,-7.006 h2.55
  text "-" at -36.292,-7.006 h2.55
  text "-" at -29.923,-7.006 h2.55
  text "-" at -23.554,-7.006 h2.55
  text "Close" at -14.637,-7.006 h2.55
  text "WLAN_SD1_D6" at 32.132,-8.505 h0.9
  text "14" at 36.074,-8.505 h0.9
  text "13" at 39.453,-8.505 h0.9
  text "WL_HOST_WAKE" at 51.9,-8.5 h0.9
  text "SAI1_RXD3" at 65.921,-8.505 h0.9
  text "14" at 69.863,-8.505 h0.9
  text "13" at 73.242,-8.505 h0.9
  text "SAI1_TXD3" at 83.378,-8.505 h0.9
  text "WLAN_SD1_D7" at 32.132,-10.758 h0.9
  text "16" at 36.074,-10.758 h0.9
  text "15" at 39.453,-10.758 h0.9
  text "SAI1_RXD4" at 65.921,-10.758 h0.9
  text "16" at 69.863,-10.758 h0.9
  text "15" at 73.242,-10.758 h0.9
  text "SAI1_TXD4" at 83.378,-10.758 h0.9
  text "WL_DEV_WAKE" at 51.9,-10.8 h0.9
  text "WLAN_SD1_CLK" at 51.9,-13 h0.9
  text "GND" at 32.132,-13.01 h0.9
  text "18" at 36.074,-13.01 h0.9
  text "17" at 39.453,-13.01 h0.9
  text "SAI1_RXD5" at 65.921,-13.01 h0.9
  text "18" at 69.863,-13.01 h0.9
  text "17" at 73.242,-13.01 h0.9
  text "SAI1_TXD5" at 83.378,-13.01 h0.9
  text "GND" at 32.132,-15.263 h0.9
  text "20" at 36.074,-15.263 h0.9
  text "19" at 39.453,-15.263 h0.9
  text "SAI1_RXD6" at 65.921,-15.263 h0.9
  text "20" at 69.863,-15.263 h0.9
  text "19" at 73.242,-15.263 h0.9
  text "SAI1_TXD6" at 83.378,-15.263 h0.9
  text "WLAN_SD1_CMD" at 51.9,-15.3 h0.9
  text "SAI1_RXD7" at 65.921,-17.515 h0.9
  text "22" at 69.863,-17.515 h0.9
  text "21" at 73.242,-17.515 h0.9
  text "SAI1_TXD7" at 83.378,-17.515 h0.9
  text "GND" at 65.921,-19.768 h0.9
  text "24" at 69.863,-19.768 h0.9
  text "23" at 73.242,-19.768 h0.9
  text "SAI1_MCLK" at 83.378,-19.768 h0.9
  text "J50" at 14.704,-33.11 h2.26
  text "J46" at 32.808,-33.11 h2.26
  text "J43" at 50.912,-33.11 h2.26
  text "J28" at 69.016,-33.11 h2.26
  text "GPIO1_IO10" at 38.4,-35.9 h0.91
  text "1" at 10.178,-35.939 h0.91
  text "CLKIN1" at 17.532,-35.939 h0.91
  text "1" at 28.282,-35.939 h0.91
  text "1" at 46.386,-35.939 h0.91
  text "VCC_MCA" at 54.872,-35.939 h0.91
  text "1" at 64.49,-35.939 h0.91
  text "MIPI_CSI_DATA3_P" at 80.897,-35.939 h0.91
  text "2" at 10.178,-38.202 h0.91
  text "GND" at 15.269,-38.202 h0.91
  text "2" at 28.282,-38.202 h0.91
  text "GPIO1_IO11" at 38.4,-38.2 h0.91
  text "2" at 46.386,-38.202 h0.91
  text "POWER_BUTTON" at 59.398,-38.202 h0.91
  text "2" at 64.49,-38.202 h0.91
  text "MIPI_CSI_DATA3_N" at 80.897,-38.202 h0.91
  text "GPIO1_IO13" at 38.4,-40.4 h0.91
  text "3" at 10.178,-40.465 h0.91
  text "CLKIN2" at 17.532,-40.465 h0.91
  text "3" at 28.282,-40.465 h0.91
  text "3" at 46.386,-40.465 h0.91
  text "SYS_RESET" at 56.569,-40.465 h0.91
  text "3" at 64.49,-40.465 h0.91
  text "GND" at 69.582,-40.465 h0.91
  text "GPIO1_IO14" at 38.4,-42.7 h0.91
  text "4" at 10.178,-42.728 h0.91
  text "GND" at 15.269,-42.728 h0.91
  text "4" at 28.282,-42.728 h0.91
  text "4" at 46.386,-42.728 h0.91
  text "MCA_CLKOUT32K" at 60.53,-42.728 h0.91
  text "4" at 64.49,-42.728 h0.91
  text "MIPI_CSI_DATA2_P" at 80.897,-42.728 h0.91
  text "5" at 10.178,-44.991 h0.91
  text "CLKOUT1" at 18.664,-44.991 h0.91
  text "5" at 28.282,-44.991 h0.91
  text "GPIO1_IO15" at 38.4,-45 h0.91
  text "5" at 46.386,-44.991 h0.91
  text "GND" at 51.478,-44.991 h0.91
  text "5" at 64.49,-44.991 h0.91
  text "MIPI_CSI_DATA2_N" at 80.897,-44.991 h0.91
  text "6" at 10.178,-47.254 h0.91
  text "GND" at 15.269,-47.254 h0.91
  text "6" at 28.282,-47.254 h0.91
  text "GND" at 33.373,-47.254 h0.91
  text "6" at 46.386,-47.254 h0.91
  text "MCA_VREF_OUT" at 59.398,-47.254 h0.91
  text "6" at 64.49,-47.254 h0.91
  text "GND" at 69.582,-47.254 h0.91
  text "7" at 10.178,-49.517 h0.91
  text "CLKOUT2" at 18.664,-49.517 h0.91
  text "8" at 10.178,-51.78 h0.91
  text "GND" at 15.269,-51.78 h0.91
Board Outline:
  the board outline again, w0.25
Top Assembly:
  circle w0.2: c136.25,61.25 r6.715
  lines w0.2: -37,-46.27 -37,-43.73
  lines w0.3: -68.27,-11.73 -65.73,-14.27
Fab/Dimension:
  lines w0.2: 137,26.925 154.075,26.925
